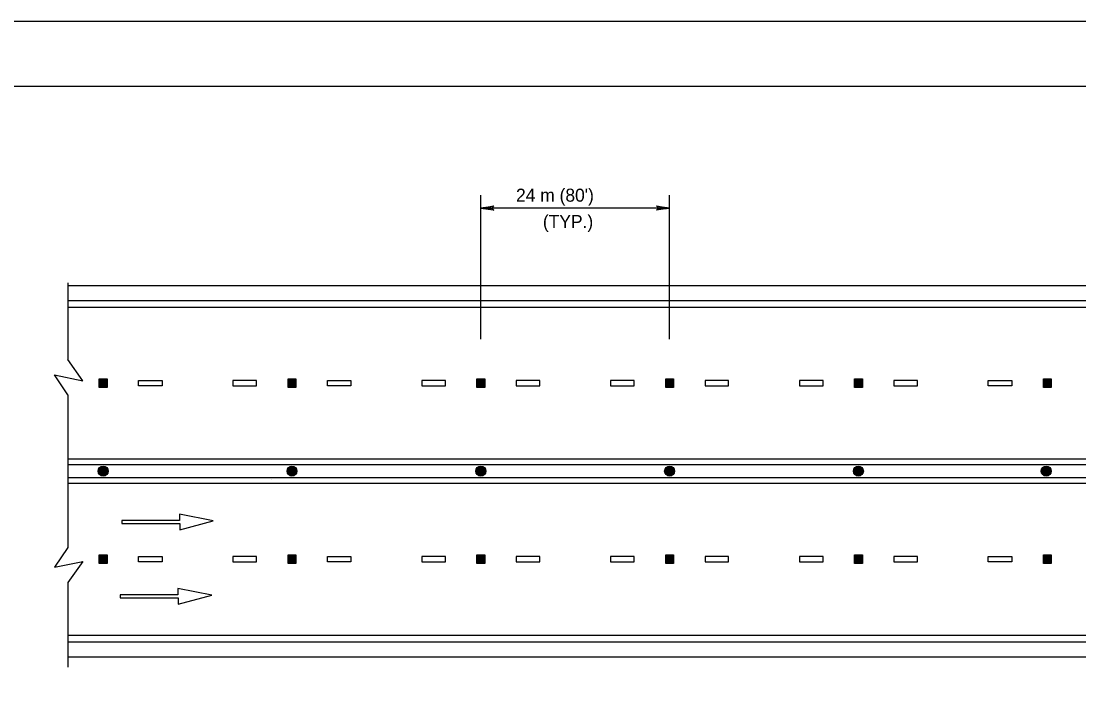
# Model space of a CAD drawing. Extents: x 639362 to 641108, y 298458 to 299646.
# Drawn here: x 640558.2 to 640801.8, y 299493.8 to 299645.6 of the extents above; entities that cross this region are included whole.
import ezdxf

# ---------------------------------------------------------------- set-up
doc = ezdxf.new("R2010")
doc.units = 0
for name, color, linetype in [('1', 7, 'Continuous'), ('2', 7, 'Continuous'), ('3', 7, 'Continuous'), ('PLT-BNDY', 7, 'Continuous')]:
    doc.layers.add(name, color=color, linetype=linetype)

# ---------------------------------------------------------------- blocks, each defined once
blk = doc.blocks.new('RARROW')
at = {"layer": '3'}
blk.add_lwpolyline([(-2.2695, 0.285), (-2.184875, 0.12075), (0, 0), (-2.2695, 0.285), (-2.38575, 0.384625), (0, 0), (-2.183125, -0.108), (-2.262875, -0.2705), (0, 0), (-2.38575, -0.379125), (-2.262875, -0.2705)], dxfattribs=at)

msp = doc.modelspace()

# ---------------------------------------------------------------- linework, layer by layer
at = {"layer": '1'}
msp.add_line((640243.31, 299630.63), (641029.31, 299630.63), dxfattribs=at)
at = {"layer": '2'}
for p, q in [((640664.07, 299572.37), (640664.07, 299605.55)), ((640707.56, 299572.37), (640707.56, 299605.55)), ((640707.56, 299602.55), (640664.07, 299602.55)), ((640568.94, 299585.28), (640568.94, 299567.63)), ((640568.94, 299584.74), (640846.38, 299584.74)), ((640568.94, 299581.24), (640846.38, 299581.24)), ((640568.94, 299579.74), (640846.38, 299579.74)), ((640572.43, 299562.73), (640568.94, 299567.63)), ((640568.94, 299559.5), (640565.89, 299564.08)), ((640565.89, 299564.08), (640572.43, 299562.73)), ((640576.2, 299563.23), (640577.97, 299563.23)), ((640576.2, 299561.19), (640576.2, 299563.23)), ((640577.97, 299561.19), (640576.2, 299561.19)), ((640576.37, 299563.05), (640577.79, 299563.05)), ((640576.37, 299561.36), (640576.37, 299563.05)), ((640577.79, 299561.36), (640576.37, 299561.36)), ((640576.55, 299562.87), (640577.62, 299562.87)), ((640576.55, 299561.54), (640576.55, 299562.87)), ((640577.62, 299561.54), (640576.55, 299561.54)), ((640576.73, 299561.72), (640576.73, 299562.69)), ((640576.73, 299562.69), (640577.44, 299562.69)), ((640577.44, 299561.72), (640576.73, 299561.72)), ((640576.91, 299562.52), (640577.26, 299562.52)), ((640576.91, 299561.9), (640576.91, 299562.52)), ((640577.26, 299561.9), (640576.91, 299561.9)), ((640577.08, 299562.34), (640577.08, 299562.07)), ((640577.26, 299562.52), (640577.26, 299561.9)), ((640577.44, 299562.69), (640577.44, 299561.72)), ((640577.62, 299562.87), (640577.62, 299561.54)), ((640577.79, 299563.05), (640577.79, 299561.36)), ((640577.97, 299563.23), (640577.97, 299561.19)), ((640585.24, 299562.81), (640590.67, 299562.81)), ((640585.24, 299561.61), (640585.24, 299562.81)), ((640590.67, 299561.61), (640585.24, 299561.61)), ((640590.67, 299562.81), (640590.67, 299561.61)), ((640612.42, 299562.81), (640606.98, 299562.81)), ((640606.98, 299562.81), (640606.98, 299561.61)), ((640606.98, 299561.61), (640612.42, 299561.61)), ((640612.42, 299561.61), (640612.42, 299562.81)), ((640619.69, 299563.23), (640621.47, 299563.23)), ((640619.69, 299561.19), (640619.69, 299563.23)), ((640621.47, 299561.19), (640619.69, 299561.19)), ((640619.87, 299563.05), (640621.29, 299563.05)), ((640619.87, 299561.36), (640619.87, 299563.05)), ((640621.29, 299561.36), (640619.87, 299561.36)), ((640620.05, 299562.87), (640621.11, 299562.87)), ((640620.05, 299561.54), (640620.05, 299562.87)), ((640621.11, 299561.54), (640620.05, 299561.54)), ((640620.22, 299561.72), (640620.22, 299562.69)), ((640620.22, 299562.69), (640620.93, 299562.69)), ((640620.93, 299561.72), (640620.22, 299561.72)), ((640620.4, 299562.52), (640620.76, 299562.52)), ((640620.4, 299561.9), (640620.4, 299562.52)), ((640620.76, 299561.9), (640620.4, 299561.9)), ((640620.58, 299562.34), (640620.58, 299562.07)), ((640620.76, 299562.52), (640620.76, 299561.9)), ((640620.93, 299562.69), (640620.93, 299561.72)), ((640621.11, 299562.87), (640621.11, 299561.54)), ((640621.29, 299563.05), (640621.29, 299561.36)), ((640621.47, 299563.23), (640621.47, 299561.19)), ((640628.73, 299562.81), (640634.17, 299562.81)), ((640628.73, 299561.61), (640628.73, 299562.81)), ((640634.17, 299561.61), (640628.73, 299561.61)), ((640634.17, 299562.81), (640634.17, 299561.61)), ((640655.91, 299562.81), (640650.48, 299562.81)), ((640650.48, 299562.81), (640650.48, 299561.61)), ((640650.48, 299561.61), (640655.91, 299561.61)), ((640655.91, 299561.61), (640655.91, 299562.81)), ((640663.18, 299563.23), (640664.96, 299563.23)), ((640663.18, 299561.19), (640663.18, 299563.23)), ((640664.96, 299561.19), (640663.18, 299561.19)), ((640663.36, 299563.05), (640664.78, 299563.05)), ((640663.36, 299561.36), (640663.36, 299563.05)), ((640664.78, 299561.36), (640663.36, 299561.36)), ((640663.54, 299562.87), (640664.6, 299562.87)), ((640663.54, 299561.54), (640663.54, 299562.87)), ((640664.6, 299561.54), (640663.54, 299561.54)), ((640663.72, 299561.72), (640663.72, 299562.69)), ((640663.72, 299562.69), (640664.43, 299562.69)), ((640664.43, 299561.72), (640663.72, 299561.72)), ((640663.89, 299562.52), (640664.25, 299562.52)), ((640663.89, 299561.9), (640663.89, 299562.52)), ((640664.25, 299561.9), (640663.89, 299561.9)), ((640664.07, 299562.34), (640664.07, 299562.07)), ((640664.25, 299562.52), (640664.25, 299561.9)), ((640664.43, 299562.69), (640664.43, 299561.72)), ((640664.6, 299562.87), (640664.6, 299561.54)), ((640664.78, 299563.05), (640664.78, 299561.36)), ((640664.96, 299563.23), (640664.96, 299561.19)), ((640677.66, 299562.81), (640672.22, 299562.81)), ((640672.22, 299562.81), (640672.22, 299561.61)), ((640672.22, 299561.61), (640677.66, 299561.61)), ((640677.66, 299561.61), (640677.66, 299562.81)), ((640699.41, 299562.81), (640693.97, 299562.81)), ((640693.97, 299562.81), (640693.97, 299561.61)), ((640693.97, 299561.61), (640699.41, 299561.61)), ((640699.41, 299561.61), (640699.41, 299562.81)), ((640706.68, 299563.23), (640708.45, 299563.23)), ((640706.68, 299561.19), (640706.68, 299563.23)), ((640708.45, 299561.19), (640706.68, 299561.19)), ((640706.85, 299563.05), (640708.27, 299563.05)), ((640706.85, 299561.36), (640706.85, 299563.05)), ((640708.27, 299561.36), (640706.85, 299561.36)), ((640707.03, 299562.87), (640708.1, 299562.87)), ((640707.03, 299561.54), (640707.03, 299562.87)), ((640708.1, 299561.54), (640707.03, 299561.54)), ((640707.21, 299561.72), (640707.21, 299562.69)), ((640707.21, 299562.69), (640707.92, 299562.69)), ((640707.92, 299561.72), (640707.21, 299561.72)), ((640707.39, 299562.52), (640707.74, 299562.52)), ((640707.39, 299561.9), (640707.39, 299562.52)), ((640707.74, 299561.9), (640707.39, 299561.9)), ((640707.56, 299562.34), (640707.56, 299562.07)), ((640707.74, 299562.52), (640707.74, 299561.9)), ((640707.92, 299562.69), (640707.92, 299561.72)), ((640708.1, 299562.87), (640708.1, 299561.54)), ((640708.27, 299563.05), (640708.27, 299561.36)), ((640708.45, 299563.23), (640708.45, 299561.19)), ((640721.15, 299562.81), (640715.72, 299562.81)), ((640715.72, 299562.81), (640715.72, 299561.61)), ((640715.72, 299561.61), (640721.15, 299561.61)), ((640721.15, 299561.61), (640721.15, 299562.81)), ((640742.9, 299562.81), (640737.46, 299562.81)), ((640737.46, 299562.81), (640737.46, 299561.61)), ((640737.46, 299561.61), (640742.9, 299561.61)), ((640742.9, 299561.61), (640742.9, 299562.81)), ((640750.17, 299563.23), (640751.95, 299563.23)), ((640750.17, 299561.19), (640750.17, 299563.23)), ((640751.95, 299561.19), (640750.17, 299561.19)), ((640750.35, 299563.05), (640751.77, 299563.05)), ((640750.35, 299561.36), (640750.35, 299563.05)), ((640751.77, 299561.36), (640750.35, 299561.36)), ((640750.53, 299562.87), (640751.59, 299562.87)), ((640750.53, 299561.54), (640750.53, 299562.87)), ((640751.59, 299561.54), (640750.53, 299561.54)), ((640750.7, 299561.72), (640750.7, 299562.69)), ((640750.7, 299562.69), (640751.41, 299562.69)), ((640751.41, 299561.72), (640750.7, 299561.72)), ((640750.88, 299562.52), (640751.23, 299562.52)), ((640750.88, 299561.9), (640750.88, 299562.52)), ((640751.23, 299561.9), (640750.88, 299561.9)), ((640751.06, 299562.34), (640751.06, 299562.07)), ((640751.23, 299562.52), (640751.23, 299561.9)), ((640751.41, 299562.69), (640751.41, 299561.72)), ((640751.59, 299562.87), (640751.59, 299561.54)), ((640751.77, 299563.05), (640751.77, 299561.36)), ((640751.95, 299563.23), (640751.95, 299561.19)), ((640764.65, 299562.81), (640759.21, 299562.81)), ((640759.21, 299562.81), (640759.21, 299561.61)), ((640759.21, 299561.61), (640764.65, 299561.61)), ((640764.65, 299561.61), (640764.65, 299562.81)), ((640780.96, 299562.81), (640786.39, 299562.81)), ((640780.96, 299561.61), (640780.96, 299562.81)), ((640786.39, 299561.61), (640780.96, 299561.61)), ((640786.39, 299562.81), (640786.39, 299561.61)), ((640793.66, 299563.23), (640795.44, 299563.23)), ((640793.66, 299561.19), (640793.66, 299563.23)), ((640795.44, 299561.19), (640793.66, 299561.19)), ((640793.84, 299563.05), (640795.26, 299563.05)), ((640793.84, 299561.36), (640793.84, 299563.05)), ((640795.26, 299561.36), (640793.84, 299561.36)), ((640794.02, 299562.87), (640795.08, 299562.87)), ((640794.02, 299561.54), (640794.02, 299562.87)), ((640795.08, 299561.54), (640794.02, 299561.54)), ((640794.2, 299561.72), (640794.2, 299562.69)), ((640794.2, 299562.69), (640794.91, 299562.69)), ((640794.91, 299561.72), (640794.2, 299561.72)), ((640794.37, 299562.52), (640794.73, 299562.52)), ((640794.37, 299561.9), (640794.37, 299562.52)), ((640794.73, 299561.9), (640794.37, 299561.9)), ((640794.55, 299562.34), (640794.55, 299562.07)), ((640794.73, 299562.52), (640794.73, 299561.9)), ((640794.91, 299562.69), (640794.91, 299561.72)), ((640795.08, 299562.87), (640795.08, 299561.54)), ((640795.26, 299563.05), (640795.26, 299561.36)), ((640795.44, 299563.23), (640795.44, 299561.19)), ((640568.94, 299559.5), (640568.94, 299524.36)), ((640846.38, 299544.68), (640568.94, 299544.68)), ((640568.94, 299544.68), (640568.94, 299543.48)), ((640568.94, 299543.48), (640846.38, 299543.48)), ((640846.38, 299540.38), (640568.94, 299540.38)), ((640568.94, 299540.38), (640568.94, 299539.18)), ((640568.94, 299539.18), (640846.38, 299539.18)), ((640615.94, 299540.06), (640615.94, 299540.06)), ((640615.94, 299540.06), (640615.94, 299540.06)), ((640602.45, 299530.5), (640594.65, 299531.98)), ((640594.65, 299531.98), (640594.65, 299530.53)), ((640594.65, 299530.53), (640581.4, 299530.53)), ((640581.4, 299530.53), (640581.4, 299529.83)), ((640581.4, 299529.83), (640594.73, 299529.83)), ((640594.73, 299528.38), (640602.45, 299530.5)), ((640594.73, 299529.83), (640594.73, 299528.38)), ((640568.94, 299524.36), (640565.89, 299519.78)), ((640576.2, 299522.67), (640577.97, 299522.67)), ((640576.2, 299520.63), (640576.2, 299522.67)), ((640576.37, 299522.49), (640577.79, 299522.49)), ((640576.37, 299520.81), (640576.37, 299522.49)), ((640576.55, 299522.31), (640577.62, 299522.31)), ((640576.55, 299520.98), (640576.55, 299522.31)), ((640576.73, 299521.16), (640576.73, 299522.14)), ((640576.73, 299522.14), (640577.44, 299522.14)), ((640576.91, 299521.96), (640577.26, 299521.96)), ((640576.91, 299521.34), (640576.91, 299521.96)), ((640577.26, 299521.96), (640577.26, 299521.34)), ((640577.44, 299522.14), (640577.44, 299521.16)), ((640577.62, 299522.31), (640577.62, 299520.98)), ((640577.79, 299522.49), (640577.79, 299520.81)), ((640577.97, 299522.67), (640577.97, 299520.63)), ((640585.24, 299522.25), (640590.67, 299522.25)), ((640585.24, 299521.05), (640585.24, 299522.25)), ((640590.67, 299522.25), (640590.67, 299521.05)), ((640612.42, 299522.25), (640606.98, 299522.25)), ((640606.98, 299522.25), (640606.98, 299521.05)), ((640612.42, 299521.05), (640612.42, 299522.25)), ((640619.69, 299522.67), (640621.47, 299522.67)), ((640619.69, 299520.63), (640619.69, 299522.67)), ((640619.87, 299522.49), (640621.29, 299522.49)), ((640619.87, 299520.81), (640619.87, 299522.49)), ((640620.05, 299522.31), (640621.11, 299522.31)), ((640620.05, 299520.98), (640620.05, 299522.31)), ((640620.22, 299521.16), (640620.22, 299522.14)), ((640620.22, 299522.14), (640620.93, 299522.14)), ((640620.4, 299521.96), (640620.76, 299521.96)), ((640620.4, 299521.34), (640620.4, 299521.96)), ((640620.76, 299521.96), (640620.76, 299521.34)), ((640620.93, 299522.14), (640620.93, 299521.16)), ((640621.11, 299522.31), (640621.11, 299520.98)), ((640621.29, 299522.49), (640621.29, 299520.81)), ((640621.47, 299522.67), (640621.47, 299520.63)), ((640628.73, 299522.25), (640634.17, 299522.25)), ((640628.73, 299521.05), (640628.73, 299522.25)), ((640634.17, 299522.25), (640634.17, 299521.05)), ((640655.91, 299522.25), (640650.48, 299522.25)), ((640650.48, 299522.25), (640650.48, 299521.05)), ((640655.91, 299521.05), (640655.91, 299522.25)), ((640663.18, 299522.67), (640664.96, 299522.67)), ((640663.18, 299520.63), (640663.18, 299522.67)), ((640663.36, 299522.49), (640664.78, 299522.49)), ((640663.36, 299520.81), (640663.36, 299522.49)), ((640663.54, 299522.31), (640664.6, 299522.31)), ((640663.54, 299520.98), (640663.54, 299522.31)), ((640663.72, 299521.16), (640663.72, 299522.14)), ((640663.72, 299522.14), (640664.43, 299522.14)), ((640663.89, 299521.96), (640664.25, 299521.96)), ((640663.89, 299521.34), (640663.89, 299521.96)), ((640664.25, 299521.96), (640664.25, 299521.34)), ((640664.43, 299522.14), (640664.43, 299521.16)), ((640664.6, 299522.31), (640664.6, 299520.98)), ((640664.78, 299522.49), (640664.78, 299520.81)), ((640664.96, 299522.67), (640664.96, 299520.63)), ((640677.66, 299522.25), (640672.22, 299522.25)), ((640672.22, 299522.25), (640672.22, 299521.05)), ((640677.66, 299521.05), (640677.66, 299522.25)), ((640699.41, 299522.25), (640693.97, 299522.25)), ((640693.97, 299522.25), (640693.97, 299521.05)), ((640699.41, 299521.05), (640699.41, 299522.25)), ((640706.68, 299522.67), (640708.45, 299522.67)), ((640706.68, 299520.63), (640706.68, 299522.67)), ((640706.85, 299522.49), (640708.27, 299522.49)), ((640706.85, 299520.81), (640706.85, 299522.49)), ((640707.03, 299522.31), (640708.1, 299522.31)), ((640707.03, 299520.98), (640707.03, 299522.31)), ((640707.21, 299521.16), (640707.21, 299522.14)), ((640707.21, 299522.14), (640707.92, 299522.14)), ((640707.39, 299521.96), (640707.74, 299521.96)), ((640707.39, 299521.34), (640707.39, 299521.96)), ((640707.74, 299521.96), (640707.74, 299521.34)), ((640707.92, 299522.14), (640707.92, 299521.16)), ((640708.1, 299522.31), (640708.1, 299520.98)), ((640708.27, 299522.49), (640708.27, 299520.81)), ((640708.45, 299522.67), (640708.45, 299520.63)), ((640721.15, 299522.25), (640715.72, 299522.25)), ((640715.72, 299522.25), (640715.72, 299521.05)), ((640721.15, 299521.05), (640721.15, 299522.25)), ((640742.9, 299522.25), (640737.46, 299522.25)), ((640737.46, 299522.25), (640737.46, 299521.05)), ((640742.9, 299521.05), (640742.9, 299522.25)), ((640750.17, 299522.67), (640751.95, 299522.67)), ((640750.17, 299520.63), (640750.17, 299522.67)), ((640750.35, 299522.49), (640751.77, 299522.49)), ((640750.35, 299520.81), (640750.35, 299522.49)), ((640750.53, 299522.31), (640751.59, 299522.31)), ((640750.53, 299520.98), (640750.53, 299522.31)), ((640750.7, 299521.16), (640750.7, 299522.14)), ((640750.7, 299522.14), (640751.41, 299522.14)), ((640750.88, 299521.96), (640751.23, 299521.96)), ((640750.88, 299521.34), (640750.88, 299521.96)), ((640751.23, 299521.96), (640751.23, 299521.34)), ((640751.41, 299522.14), (640751.41, 299521.16)), ((640751.59, 299522.31), (640751.59, 299520.98)), ((640751.77, 299522.49), (640751.77, 299520.81)), ((640751.95, 299522.67), (640751.95, 299520.63)), ((640764.65, 299522.25), (640759.21, 299522.25)), ((640759.21, 299522.25), (640759.21, 299521.05)), ((640764.65, 299521.05), (640764.65, 299522.25)), ((640780.96, 299522.25), (640786.39, 299522.25)), ((640780.96, 299521.05), (640780.96, 299522.25)), ((640786.39, 299522.25), (640786.39, 299521.05)), ((640793.66, 299522.67), (640795.44, 299522.67)), ((640793.66, 299520.63), (640793.66, 299522.67)), ((640793.84, 299522.49), (640795.26, 299522.49)), ((640793.84, 299520.81), (640793.84, 299522.49)), ((640794.02, 299522.31), (640795.08, 299522.31)), ((640794.02, 299520.98), (640794.02, 299522.31)), ((640794.2, 299521.16), (640794.2, 299522.14)), ((640794.2, 299522.14), (640794.91, 299522.14)), ((640794.37, 299521.96), (640794.73, 299521.96)), ((640794.37, 299521.34), (640794.37, 299521.96)), ((640794.73, 299521.96), (640794.73, 299521.34)), ((640794.91, 299522.14), (640794.91, 299521.16)), ((640795.08, 299522.31), (640795.08, 299520.98)), ((640795.26, 299522.49), (640795.26, 299520.81)), ((640795.44, 299522.67), (640795.44, 299520.63)), ((640565.89, 299519.78), (640572.43, 299521.13)), ((640572.43, 299521.13), (640568.94, 299516.24)), ((640577.97, 299520.63), (640576.2, 299520.63)), ((640577.79, 299520.81), (640576.37, 299520.81)), ((640577.62, 299520.98), (640576.55, 299520.98)), ((640577.44, 299521.16), (640576.73, 299521.16)), ((640577.26, 299521.34), (640576.91, 299521.34)), ((640577.08, 299521.78), (640577.08, 299521.51)), ((640590.67, 299521.05), (640585.24, 299521.05)), ((640606.98, 299521.05), (640612.42, 299521.05)), ((640621.47, 299520.63), (640619.69, 299520.63)), ((640621.29, 299520.81), (640619.87, 299520.81)), ((640621.11, 299520.98), (640620.05, 299520.98)), ((640620.93, 299521.16), (640620.22, 299521.16)), ((640620.76, 299521.34), (640620.4, 299521.34)), ((640620.58, 299521.78), (640620.58, 299521.51)), ((640634.17, 299521.05), (640628.73, 299521.05)), ((640650.48, 299521.05), (640655.91, 299521.05)), ((640664.96, 299520.63), (640663.18, 299520.63)), ((640664.78, 299520.81), (640663.36, 299520.81)), ((640664.6, 299520.98), (640663.54, 299520.98)), ((640664.43, 299521.16), (640663.72, 299521.16)), ((640664.25, 299521.34), (640663.89, 299521.34)), ((640664.07, 299521.78), (640664.07, 299521.51)), ((640672.22, 299521.05), (640677.66, 299521.05)), ((640693.97, 299521.05), (640699.41, 299521.05)), ((640708.45, 299520.63), (640706.68, 299520.63)), ((640708.27, 299520.81), (640706.85, 299520.81)), ((640708.1, 299520.98), (640707.03, 299520.98)), ((640707.92, 299521.16), (640707.21, 299521.16)), ((640707.74, 299521.34), (640707.39, 299521.34)), ((640707.56, 299521.78), (640707.56, 299521.51)), ((640715.72, 299521.05), (640721.15, 299521.05)), ((640737.46, 299521.05), (640742.9, 299521.05)), ((640751.95, 299520.63), (640750.17, 299520.63)), ((640751.77, 299520.81), (640750.35, 299520.81)), ((640751.59, 299520.98), (640750.53, 299520.98)), ((640751.41, 299521.16), (640750.7, 299521.16)), ((640751.23, 299521.34), (640750.88, 299521.34)), ((640751.06, 299521.78), (640751.06, 299521.51)), ((640759.21, 299521.05), (640764.65, 299521.05)), ((640786.39, 299521.05), (640780.96, 299521.05)), ((640795.44, 299520.63), (640793.66, 299520.63)), ((640795.26, 299520.81), (640793.84, 299520.81)), ((640795.08, 299520.98), (640794.02, 299520.98)), ((640794.91, 299521.16), (640794.2, 299521.16)), ((640794.73, 299521.34), (640794.37, 299521.34)), ((640794.55, 299521.78), (640794.55, 299521.51)), ((640568.94, 299516.24), (640568.94, 299496.73)), ((640602.08, 299513.37), (640594.28, 299514.84)), ((640594.28, 299514.84), (640594.28, 299513.4)), ((640594.28, 299513.4), (640581.03, 299513.4)), ((640581.03, 299513.4), (640581.03, 299512.69)), ((640581.03, 299512.69), (640594.36, 299512.69)), ((640594.36, 299511.25), (640602.08, 299513.37)), ((640594.36, 299512.69), (640594.36, 299511.25)), ((640568.94, 299504.12), (640846.38, 299504.12)), ((640568.94, 299502.62), (640846.38, 299502.62)), ((640568.94, 299499.12), (640846.38, 299499.12))]:
    msp.add_line(p, q, dxfattribs=at)
for centre, radius in [((640577.09, 299541.93), 1.15), ((640577.09, 299541.93), 1.07), ((640577.09, 299541.93), 0.985), ((640577.09, 299541.93), 0.904), ((640577.09, 299541.93), 0.822), ((640577.09, 299541.93), 0.741), ((640577.09, 299541.93), 0.659), ((640577.09, 299541.93), 0.578), ((640577.09, 299541.93), 0.496), ((640577.09, 299541.93), 0.414), ((640577.09, 299541.93), 0.333), ((640577.09, 299541.93), 0.251), ((640577.09, 299541.93), 0.17), ((640577.09, 299541.93), 0.0881), ((640620.58, 299541.93), 1.15), ((640620.58, 299541.93), 1.07), ((640620.58, 299541.93), 0.985), ((640620.58, 299541.93), 0.904), ((640620.58, 299541.93), 0.822), ((640620.58, 299541.93), 0.741), ((640620.58, 299541.93), 0.659), ((640620.58, 299541.93), 0.578), ((640620.58, 299541.93), 0.496), ((640620.58, 299541.93), 0.414), ((640620.58, 299541.93), 0.333), ((640620.58, 299541.93), 0.251), ((640620.58, 299541.93), 0.17), ((640620.58, 299541.93), 0.0881), ((640664.07, 299541.93), 1.15), ((640664.07, 299541.93), 1.07), ((640664.07, 299541.93), 0.985), ((640664.07, 299541.93), 0.904), ((640664.07, 299541.93), 0.822), ((640664.07, 299541.93), 0.741), ((640664.07, 299541.93), 0.659), ((640664.07, 299541.93), 0.578), ((640664.07, 299541.93), 0.496), ((640664.07, 299541.93), 0.414), ((640664.07, 299541.93), 0.333), ((640664.07, 299541.93), 0.251), ((640664.07, 299541.93), 0.17), ((640664.07, 299541.93), 0.0881), ((640707.56, 299541.93), 1.15), ((640707.56, 299541.93), 1.07), ((640707.56, 299541.93), 0.985), ((640707.56, 299541.93), 0.904), ((640707.56, 299541.93), 0.822), ((640707.56, 299541.93), 0.741), ((640707.56, 299541.93), 0.659), ((640707.56, 299541.93), 0.578), ((640707.56, 299541.93), 0.496), ((640707.56, 299541.93), 0.414), ((640707.56, 299541.93), 0.333), ((640707.56, 299541.93), 0.251), ((640707.56, 299541.93), 0.17), ((640707.56, 299541.93), 0.0881), ((640751.03, 299541.93), 1.15), ((640751.03, 299541.93), 1.07), ((640751.03, 299541.93), 0.985), ((640751.03, 299541.93), 0.904), ((640751.03, 299541.93), 0.822), ((640751.03, 299541.93), 0.741), ((640751.03, 299541.93), 0.659), ((640751.03, 299541.93), 0.578), ((640751.03, 299541.93), 0.496), ((640751.03, 299541.93), 0.414), ((640751.03, 299541.93), 0.333), ((640751.03, 299541.93), 0.251), ((640751.03, 299541.93), 0.17), ((640751.03, 299541.93), 0.0881), ((640794.3, 299541.93), 1.15), ((640794.3, 299541.93), 1.07), ((640794.3, 299541.93), 0.985), ((640794.3, 299541.93), 0.904), ((640794.3, 299541.93), 0.822), ((640794.3, 299541.93), 0.741), ((640794.3, 299541.93), 0.659), ((640794.3, 299541.93), 0.578), ((640794.3, 299541.93), 0.496), ((640794.3, 299541.93), 0.414), ((640794.3, 299541.93), 0.333), ((640794.3, 299541.93), 0.251), ((640794.3, 299541.93), 0.17), ((640794.3, 299541.93), 0.0881)]:
    msp.add_circle(centre, radius, dxfattribs=at)
at = {"layer": 'PLT-BNDY'}
msp.add_lwpolyline([(640203.31, 299645.63), (641044.31, 299645.63), (641044.31, 299051.63), (640203.31, 299051.63)], close=True, dxfattribs=at)

# ---------------------------------------------------------------- block references
at = {"layer": '2', "xscale": 1.2574347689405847, "yscale": 1.3092961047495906, "rotation": 180}
msp.add_blockref('RARROW', (640664.07, 299602.55), dxfattribs=at)
at = {"layer": '2', "xscale": 1.2574347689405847, "yscale": 1.3092961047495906}
msp.add_blockref('RARROW', (640707.56, 299602.55), dxfattribs=at)

# ---------------------------------------------------------------- texts
at = {"layer": '2'}
for s, p in [("24 m (80')", (640672.18, 299604.02)), ('(TYP.)', (640678.37, 299597.95))]:
    msp.add_text(s, height=3, dxfattribs=at).set_placement(p)

doc.saveas('drawing.dxf')
